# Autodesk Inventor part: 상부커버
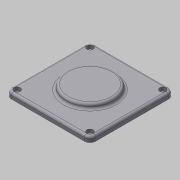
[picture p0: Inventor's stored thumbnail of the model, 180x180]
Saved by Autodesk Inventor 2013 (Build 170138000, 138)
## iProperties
Created: 2018-09
Part Number: 상부커버
Document SubType Name: Modeling
Density: 2.71 g/cm^3
Material: 알루미늄 6061
Mass: 115.614 g
Surface Area: 104.313 cm^2
Volume: 42.662 cm^3
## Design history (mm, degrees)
sketch "스케치5"
  geometry: L1 (-52.5, -52.5)-(52.5, -52.5); L2 (52.5, -52.5)-(52.5, 52.5); L3 (52.5, 52.5)-(-52.5, 52.5); L4 (-52.5, 52.5)-(-52.5, -52.5); L5 (-52.5, -52.5)-(52.5, 52.5); L6 (52.5, -52.5)-(-52.5, 52.5); 1 further point
  constraints: 12 end point, 2 midpoint, 2 parallel, 1 horizontal, 1 perpendicular
  dimensions: "d35" = 105 distance of L3.end L2.end; "d36" = 105 distance of L2.end L1.end
extrude "돌출4" new body sketch "스케치5" distance "d37" = 7; taper "d38" = 0 deg
fillet "모깎기4" dims "d39" = 7
sketch "스케치2"
  geometry: C1 r 30 at (0, 0); 2 further points
  constraints: 2 coincident, 1 centre point
  dimensions: "d4" = 60 diameter of C1
extrude "돌출3" join sketch "스케치2" distance "d5" = 6; taper "d6" = 0 deg
fillet "모깎기1" dims "d7" = 3
sketch "스케치4"
  geometry: L1 (52.5, -45.5)-(52.5, 45.5) reference; L2 (-45.5, -52.5)-(45.5, -52.5) reference; L3 (-52.5, 45.5)-(-52.5, -45.5) reference; L4 (45.5, 52.5)-(-45.5, 52.5) reference; A1 r 7 centre (45.5, 45.5) between (52.5, 45.5) and (45.5, 52.5) reference; A2 r 7 centre (45.5, -45.5) between (45.5, -52.5) and (52.5, -45.5) reference; A3 r 7 centre (-45.5, -45.5) between (-52.5, -45.5) and (-45.5, -52.5) reference; A4 r 7 centre (-45.5, 45.5) between (-45.5, 52.5) and (-52.5, 45.5) reference; 4 further points
  constraints: 4 coincident
hole "구멍3" sketch "스케치4" at (-45.5, 45.5), (-45.5, -45.5), (45.5, -45.5), (45.5, 45.5) diameter "d43" = 4.5; stored, may be unused: countersink angle "d47" = 90 deg, drill point angle "d49" = 118 deg; dims "d44" = 6, "d45" = 8, "d46" = 4.4, "d48" = 8
fillet "모깎기3" dims "d19" = 3
node "솔리드1"
node "솔리드2"
node "투영된 루프2"
